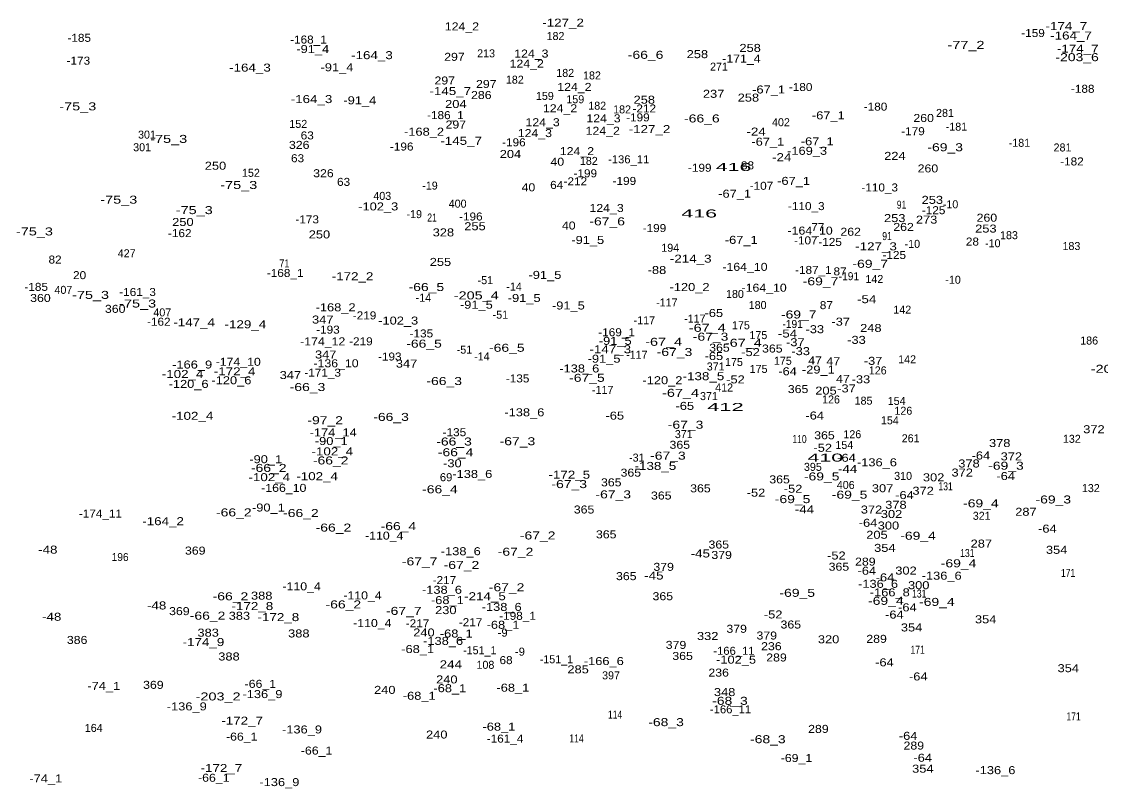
# Model space of a CAD drawing. Extents: x -658110 to -655750, y -1000429 to -997657.
# Drawn here: x -657542 to -657003, y -999113 to -998730 of the extents above; entities that cross this region are included whole.
import ezdxf
from ezdxf.enums import TextEntityAlignment as Align

# ---------------------------------------------------------------- set-up
doc = ezdxf.new("R2010")
doc.units = 0
doc.header["$LTSCALE"] = 1.6
doc.layers.add('24', color=7, linetype='Continuous')

msp = doc.modelspace()

# ---------------------------------------------------------------- texts
at = {"layer": '24'}
for s, width, p in [('124_2', 1.15, (-657322.15, -998734.24)), ('-127_2', 1.25, (-657271.59, -998732.37)), ('-174_7', 1.25, (-657020.03, -998734.08)), ('-185', 1.1, (-657513.451, -998739.96)), ('-159', 1.1, (-657036.68, -998737.56)), ('-164_7', 1.25, (-657017.691, -998738.81)), ('-168_1', 1.1, (-657398.88, -998740.82)), ('258', 1.2, (-657178.09, -998745)), ('-77_2', 1.35, (-657070.191, -998743.49)), ('-174_7', 1.25, (-657014.331, -998745.38)), ('-91_4', 1.2, (-657396.72, -998745.56)), ('-164_3', 1.25, (-657367.13, -998748.62)), ('297', 1.15, (-657325.89, -998749.45)), ('124_3', 1.15, (-657287.449, -998747.82)), ('-66_6', 1.3, (-657230.34, -998748.45)), ('258', 1.2, (-657204.459, -998748.11)), ('-171_4', 1.15, (-657182.45, -998750.33)), ('-203_6', 1.3, (-657014.64, -998749.63)), ('-173', 1.1, (-657513.88, -998751.37)), ('-164_3', 1.25, (-657428.11, -998754.84)), ('-91_4', 1.2, (-657384.62, -998754.67)), ('124_2', 1.15, (-657289.77, -998752.86)), ('297', 1.15, (-657330.74, -998761.28)), ('-145_7', 1.25, (-657327.97, -998766.56)), ('297', 1.15, (-657309.99, -998763.03)), ('124_2', 1.15, (-657265.929, -998764.49)), ('-67_1', 1.2, (-657168.86, -998765.78)), ('-180', 1.1, (-657152.851, -998764.55)), ('-188', 1.1, (-657011.841, -998765.43)), ('-164_3', 1.25, (-657397.33, -998770.57)), ('-91_4', 1.2, (-657373.19, -998771.19)), ('286', 1.15, (-657312.48, -998768.55)), ('258', 1.2, (-657231.01, -998770.89)), ('237', 1.2, (-657196.34, -998767.94)), ('258', 1.2, (-657178.959, -998769.83)), ('-75_3', 1.35, (-657514.17, -998774.22)), ('204', 1.2, (-657325.199, -998773.03)), ('124_2', 1.15, (-657273.1, -998775.16)), ('-212', 1.1, (-657231.01, -998775.27)), ('-180', 1.1, (-657115.41, -998774.34)), ('-186_1', 1.1, (-657330.421, -998778.59)), ('124_3', 1.15, (-657281.819, -998782.14)), ('124_3', 1.15, (-657251.39, -998780.2)), ('-199', 1.1, (-657234.189, -998779.72)), ('-66_6', 1.3, (-657202.22, -998780.25)), ('-67_1', 1.2, (-657139.01, -998778.69)), ('260', 1.15, (-657091.361, -998780.02)), ('-168_2', 1.2, (-657341.101, -998786.88)), ('297', 1.15, (-657325.21, -998783.29)), ('124_3', 1.15, (-657285.699, -998787.57)), ('124_2', 1.15, (-657251.77, -998786.41)), ('-127_2', 1.25, (-657228.39, -998785.57)), ('-24', 1.25, (-657175.08, -998786.81)), ('-179', 1.1, (-657096.689, -998786.63)), ('-75_3', 1.35, (-657468.72, -998790.48)), ('326', 1.15, (-657403.48, -998793.47)), ('63', 1.1, (-657399.48, -998788.73)), ('-145_7', 1.25, (-657322.55, -998791.44)), ('-196', 1.1, (-657296.189, -998792.18)), ('-67_1', 1.2, (-657169.25, -998791.87)), ('-67_1', 1.2, (-657144.54, -998791.68)), ('-196', 1.1, (-657352.26, -998794.29)), ('204', 1.2, (-657297.9, -998798.03)), ('124_2', 1.15, (-657264.66, -998796.6)), ('-169_3', 1.2, (-657149.62, -998796.43)), ('224', 1.2, (-657105.73, -998798.96)), ('-69_3', 1.3, (-657080.59, -998794.64)), ('250', 1.2, (-657445.34, -998803.88)), ('63', 1.1, (-657404.31, -998800.14)), ('40', 1.15, (-657274.48, -998801.88)), ('-136_11', 1.05, (-657238.811, -998800.68)), ('416', 2, (-657186.368, -998804.5)), ('88', 1.1, (-657179.41, -998803.69)), ('-24', 1.25, (-657162.29, -998799.61)), ('-182', 1.1, (-657017.24, -998801.74)), ('326', 1.15, (-657391.37, -998807.63)), ('-199', 1.1, (-657260.49, -998807.67)), ('-199', 1.1, (-657203.28, -998804.89)), ('260', 1.15, (-657089.231, -998805.23)), ('-75_3', 1.35, (-657433.71, -998813.5)), ('63', 1.1, (-657381.3, -998811.95)), ('40', 1.15, (-657288.919, -998814.68)), ('64', 1.1, (-657274.77, -998813.47)), ('-212', 1.1, (-657265.481, -998811.67)), ('-199', 1.1, (-657240.959, -998811.47)), ('-107', 1.1, (-657172.43, -998813.91)), ('-67_1', 1.2, (-657156.36, -998811.46)), ('-110_3', 1.1, (-657113.33, -998814.74)), ('-75_3', 1.35, (-657493.67, -998820.85)), ('-67_1', 1.2, (-657185.83, -998817.86)), ('253', 1.2, (-657087.01, -998820.94)), ('-75_3', 1.35, (-657455.95, -998826.07)), ('-102_3', 1.2, (-657363.98, -998824.22)), ('124_3', 1.15, (-657249.84, -998825)), ('-110_3', 1.1, (-657150.02, -998824.05)), ('91', 0.8, (-657102.4, -998823.33)), ('-125', 1.1, (-657086.37, -998826.11)), ('-173', 1.1, (-657399.5, -998830.69)), ('21', 0.8, (-657337.09, -998829.77)), ('-196', 1.1, (-657317.699, -998829.25)), ('-67_6', 1.3, (-657249.559, -998831.69)), ('416', 2, (-657203.548, -998827.74)), ('253', 1.2, (-657105.809, -998830.05)), ('273', 1.2, (-657089.88, -998830.82)), ('260', 1.15, (-657059.76, -998829.86)), ('-75_3', 1.35, (-657535.83, -998836.72)), ('250', 1.2, (-657461.63, -998832)), ('328', 1.2, (-657331.419, -998837.2)), ('255', 1.2, (-657315.62, -998834.12)), ('40', 1.15, (-657268.76, -998833.78)), ('-199', 1.1, (-657225.929, -998835.04)), ('-164_10', 1.15, (-657148.111, -998836.31)), ('77', 1.1, (-657144.27, -998834.56)), ('262', 1.15, (-657127.84, -998836.87)), ('262', 1.15, (-657101.4, -998834.47)), ('253', 1.2, (-657060.25, -998835.29)), ('-162', 1.1, (-657463.2, -998837.57)), ('250', 1.2, (-657393.38, -998838.21)), ('-91_5', 1.2, (-657259.26, -998840.98)), ('-67_1', 1.2, (-657182.53, -998840.93)), ('-107', 1.1, (-657150.26, -998841.19)), ('-125', 1.1, (-657138.12, -998841.96)), ('91', 0.8, (-657109.671, -998839.04)), ('28', 1.1, (-657066.98, -998841.78)), ('-127_3', 1.25, (-657115.17, -998844.18)), ('82', 1.1, (-657525.52, -998850.78)), ('71', 0.85, (-657410.941, -998852.72)), ('255', 1.2, (-657332.88, -998851.96)), ('-214_3', 1.25, (-657207.79, -998850.32)), ('-69_7', 1.3, (-657118.069, -998852.89)), ('-125', 1.1, (-657106.051, -998848.49)), ('20', 1.1, (-657513.26, -998858.56)), ('-168_1', 1.1, (-657410.51, -998857.48)), ('-91_5', 1.2, (-657280.671, -998858.45)), ('-88', 1.2, (-657224.67, -998856.01)), ('-164_10', 1.15, (-657180.671, -998854.42)), ('-187_1', 1.1, (-657146.481, -998855.96)), ('87', 1.1, (-657133.13, -998856.68)), ('-172_2', 1.25, (-657376.82, -998859.11)), ('-69_7', 1.3, (-657142.9, -998861.63)), ('-191', 0.95, (-657128.73, -998859.08)), ('-185', 1.1, (-657534.961, -998864.42)), ('-75_3', 1.35, (-657507.78, -998868.44)), ('-161_3', 1.1, (-657484.291, -998867)), ('-66_5', 1.3, (-657339.93, -998864.51)), ('-205_4', 1.35, (-657315, -998868.68)), ('-120_2', 1.2, (-657208.38, -998864.51)), ('-164_10', 1.15, (-657171.091, -998864.85)), ('360', 1.15, (-657532.841, -998869.97)), ('-75_3', 1.35, (-657484.24, -998872.75)), ('-168_2', 1.2, (-657385.291, -998874.64)), ('-91_5', 1.2, (-657314.941, -998873.34)), ('-91_5', 1.2, (-657291.041, -998869.98)), ('-91_5', 1.2, (-657268.951, -998873.73)), ('87', 1.1, (-657139.99, -998873.56)), ('-54', 1.25, (-657119.85, -998870.58)), ('360', 1.15, (-657495.461, -998875.41)), ('-219', 1.1, (-657370.83, -998878.68)), ('-65', 1.2, (-657196.24, -998877.48)), ('-69_7', 1.3, (-657153.799, -998878.22)), ('-162', 1.1, (-657473.68, -998881.84)), ('-147_4', 1.25, (-657456.01, -998882.15)), ('-129_4', 1.25, (-657430.39, -998883.12)), ('347', 1.2, (-657391.71, -998880.76)), ('-102_3', 1.2, (-657354, -998881.27)), ('-67_4', 1.35, (-657199.5, -998884.89)), ('-191', 0.95, (-657156.86, -998882.99)), ('-33', 1.2, (-657145.77, -998885.58)), ('-37', 1.2, (-657132.821, -998881.81)), ('248', 1.2, (-657117.74, -998884.96)), ('-193', 1.1, (-657389.13, -998885.8)), ('-135', 1.1, (-657342.421, -998887.7)), ('-169_1', 1.1, (-657244.84, -998887.11)), ('-67_3', 1.3, (-657197.851, -998889.31)), ('-54', 1.25, (-657159.41, -998887.74)), ('-33', 1.2, (-657124.93, -998890.92)), ('-174_12', 1.15, (-657391.73, -998891.67)), ('-219', 1.1, (-657372.66, -998891.65)), ('-66_5', 1.3, (-657341.1, -998892.81)), ('-66_5', 1.3, (-657299.71, -998894.87)), ('-147_3', 1.25, (-657248.01, -998895.62)), ('-91_5', 1.2, (-657245.53, -998891.4)), ('-67_4', 1.35, (-657221.311, -998891.88)), ('365', 1.15, (-657193.43, -998894.81)), ('-67_4', 1.35, (-657181.481, -998892.37)), ('365', 1.15, (-657167.01, -998895.25)), ('-37', 1.2, (-657155.5, -998892.09)), ('-174_10', 1.15, (-657433.98, -998901.87)), ('347', 1.2, (-657390.23, -998898.23)), ('-193', 1.1, (-657358.22, -998899.24)), ('-91_5', 1.2, (-657251.101, -998900.33)), ('-67_3', 1.3, (-657215.89, -998896.97)), ('-65', 1.2, (-657196.21, -998898.99)), ('-52', 1.2, (-657177.89, -998897.03)), ('-33', 1.2, (-657152.84, -998896.55)), ('47', 1.15, (-657145.64, -998901.2)), ('47', 1.15, (-657136.53, -998901.59)), ('-37', 1.2, (-657116.63, -998901.4)), ('-166_9', 1.2, (-657457, -998903.25)), ('-172_4', 1.25, (-657435.76, -998906.63)), ('-171_3', 1.1, (-657391.77, -998907.3)), ('-136_10', 1.15, (-657385.071, -998902.62)), ('347', 1.2, (-657349.83, -998902.77)), ('-138_6', 1.2, (-657263.49, -998905.21)), ('-64', 1.2, (-657159.38, -998906.61)), ('-29_1', 1.2, (-657144, -998905.76)), ('-203_4', 1.35, (-656996.6, -998905.38)), ('-102_4', 1.25, (-657461.78, -998907.97)), ('-120_6', 1.2, (-657437.38, -998911.1)), ('347', 1.2, (-657407.9, -998908.49)), ('-66_3', 1.3, (-657331.02, -998911.49)), ('-135', 1.1, (-657294.321, -998910.18)), ('-67_5', 1.3, (-657259.671, -998909.88)), ('-120_2', 1.2, (-657221.929, -998911.09)), ('-138_5', 1.25, (-657201.429, -998909.07)), ('-52', 1.2, (-657185.42, -998910.68)), ('47', 1.15, (-657131.68, -998910.41)), ('-33', 1.2, (-657122.71, -998910.61)), ('-120_6', 1.2, (-657458.78, -998912.93)), ('-66_3', 1.3, (-657399.35, -998914.49)), ('-67_4', 1.35, (-657212.88, -998917.39)), ('365', 1.15, (-657154.12, -998915.51)), ('205', 1.2, (-657140.179, -998916.29)), ('-37', 1.2, (-657129.91, -998915.18)), ('-102_4', 1.25, (-657456.84, -998928.88)), ('-138_6', 1.2, (-657290.951, -998927.11)), ('-65', 1.2, (-657245.74, -998928.77)), ('-65', 1.2, (-657210.75, -998923.91)), ('412', 2.05, (-657190.443, -998924.45)), ('-64', 1.2, (-657145.811, -998928.72)), ('-97_2', 1.3, (-657390.51, -998931.07)), ('-66_3', 1.3, (-657357.58, -998929.42)), ('-67_3', 1.3, (-657210.361, -998933.33)), ('-174_14', 1.2, (-657386.5, -998937.16)), ('-135', 1.1, (-657325.91, -998937.06)), ('365', 1.15, (-657140.94, -998938.59)), ('372', 1.2, (-657006.24, -998935.58)), ('-90_1', 1.2, (-657387.471, -998941.48)), ('-66_3', 1.3, (-657326.1, -998941.72)), ('-67_3', 1.3, (-657294.41, -998941.58)), ('365', 1.15, (-657213.25, -998943.35)), ('110', 0.8, (-657153.42, -998940.5)), ('-52', 1.2, (-657141.8, -998944.84)), ('378', 1.2, (-657053.34, -998942.48)), ('-102_4', 1.25, (-657386.939, -998946.65)), ('-66_4', 1.3, (-657325.311, -998947.07)), ('-67_3', 1.3, (-657219.191, -998948.77)), ('410', 2, (-657140.509, -998949.75)), ('-64', 1.2, (-657129.91, -998949.85)), ('-64', 1.2, (-657062.75, -998948.7)), ('372', 1.2, (-657047.53, -998949.15)), ('-90_1', 1.2, (-657420.221, -998950.56)), ('-66_2', 1.3, (-657418.72, -998954.91)), ('-66_2', 1.3, (-657387.75, -998951.17)), ('-30', 1.2, (-657326.92, -998952.59)), ('-138_5', 1.25, (-657225.439, -998953.92)), ('-44', 1.25, (-657129.36, -998955.44)), ('-136_6', 1.2, (-657114.71, -998952.11)), ('378', 1.2, (-657068.7, -998952.69)), ('-69_3', 1.3, (-657050.21, -998953.81)), ('-102_4', 1.25, (-657418.439, -998959.53)), ('-102_4', 1.25, (-657394.53, -998959.04)), ('69', 1.05, (-657330.07, -998959.55)), ('-138_6', 1.2, (-657316.971, -998957.93)), ('-172_5', 1.25, (-657268.48, -998958.3)), ('365', 1.15, (-657237.73, -998957.27)), ('365', 1.15, (-657163.38, -998960.65)), ('-69_5', 1.3, (-657142.33, -998959.16)), ('302', 1.2, (-657086.37, -998959.62)), ('372', 1.2, (-657072.07, -998957.22)), ('-64', 1.2, (-657050.351, -998958.98)), ('-166_10', 1.15, (-657411.199, -998964.89)), ('-66_4', 1.3, (-657333.16, -998965.59)), ('-67_3', 1.3, (-657268.52, -998963)), ('365', 1.15, (-657247.52, -998962.12)), ('365', 1.15, (-657202.93, -998965.11)), ('-52', 1.2, (-657156.63, -998965.32)), ('307', 1.2, (-657111.89, -998965.07)), ('372', 1.2, (-657091.63, -998966.32)), ('131', 0.8, (-657080.39, -998964.09)), ('-67_3', 1.3, (-657246.52, -998968.14)), ('365', 1.15, (-657222.51, -998968.72)), ('-52', 1.2, (-657175.16, -998967.27)), ('-69_5', 1.3, (-657156.87, -998970.51)), ('-69_5', 1.3, (-657128.38, -998968.28)), ('-64', 1.2, (-657100.941, -998968.48)), ('-69_3', 1.3, (-657026.56, -998970.68)), ('-66_2', 1.3, (-657436.18, -998977.15)), ('-90_1', 1.2, (-657418.89, -998974.71)), ('365', 1.15, (-657261.09, -998975.7)), ('-44', 1.25, (-657150.91, -998975.63)), ('372', 1.2, (-657117.42, -998975.72)), ('378', 1.2, (-657105.22, -998973.33)), ('-69_4', 1.3, (-657062.75, -998972.61)), ('287', 1.2, (-657040.23, -998976.82)), ('-174_11', 1.1, (-657502.87, -998977.75)), ('-164_2', 1.25, (-657471.53, -998981.53)), ('-66_2', 1.3, (-657402.65, -998977.46)), ('-64', 1.2, (-657119.15, -998982.34)), ('302', 1.2, (-657107.41, -998977.95)), ('-66_2', 1.3, (-657386.39, -998984.73)), ('-66_4', 1.3, (-657353.9, -998984.01)), ('365', 1.15, (-657250.04, -998988.11)), ('300', 1.2, (-657108.959, -998983.7)), ('-64', 1.2, (-657029.51, -998985.26)), ('-110_4', 1.15, (-657360.99, -998988.74)), ('-67_2', 1.3, (-657284.301, -998988.67)), ('365', 1.15, (-657193.77, -998993.2)), ('205', 1.2, (-657114.689, -998988.32)), ('-69_4', 1.3, (-657094.16, -998988.81)), ('287', 1.2, (-657062.52, -998992.73)), ('-48', 1.25, (-657529.16, -998995.74)), ('369', 1.15, (-657455.46, -998996.23)), ('-138_6', 1.2, (-657322.731, -998996.54)), ('-67_2', 1.3, (-657295.351, -998996.81)), ('-45', 1.25, (-657202.99, -998997.67)), ('379', 1.15, (-657192.33, -998998.41)), ('-52', 1.2, (-657134.98, -998998.69)), ('354', 1.2, (-657110.76, -998994.88)), ('131', 0.8, (-657069.53, -998997.45)), ('354', 1.2, (-657024.88, -998995.85)), ('196', 0.95, (-657493, -998999.45)), ('-67_7', 1.3, (-657343.28, -999001.64)), ('-67_2', 1.3, (-657322.39, -999003.41)), ('379', 1.15, (-657221.32, -999004.35)), ('365', 1.15, (-657133.72, -999004.29)), ('289', 1.15, (-657120.51, -999001.75)), ('-69_4', 1.3, (-657073.9, -999002.58)), ('365', 1.15, (-657240.01, -999009)), ('-45', 1.25, (-657226.2, -999008.7)), ('-64', 1.2, (-657119.76, -999006.29)), ('-64', 1.2, (-657110.691, -999009.63)), ('302', 1.2, (-657100.179, -999006.22)), ('-136_6', 1.2, (-657082.35, -999008.77)), ('171', 0.8, (-657019.14, -999007.37)), ('-110_4', 1.15, (-657402.28, -999014.09)), ('-217', 1.1, (-657330.9, -999010.98)), ('-67_2', 1.3, (-657299.821, -999014.56)), ('-136_6', 1.2, (-657114.15, -999012.84)), ('300', 1.2, (-657093.829, -999013.52)), ('-66_2', 1.3, (-657437.86, -999019.07)), ('388', 1.2, (-657422.23, -999018.73)), ('-110_4', 1.15, (-657371.84, -999018.61)), ('-138_6', 1.2, (-657332.14, -999015.82)), ('-214_5', 1.25, (-657310.63, -999019.04)), ('365', 1.15, (-657221.74, -999019.03)), ('-69_5', 1.3, (-657154.55, -999017.35)), ('-166_8', 1.2, (-657108.29, -999017.11)), ('131', 0.8, (-657093.57, -999017.71)), ('-48', 1.25, (-657474.74, -999023.65)), ('-172_8', 1.25, (-657426.89, -999023.95)), ('-66_2', 1.3, (-657381.44, -999023.13)), ('-68_1', 1.2, (-657329.431, -999020.98)), ('-138_6', 1.2, (-657302.28, -999024.38)), ('-69_4', 1.3, (-657110.25, -999021.34)), ('-64', 1.2, (-657099.481, -999024.6)), ('-69_4', 1.3, (-657084.75, -999021.88)), ('-48', 1.25, (-657527.21, -999029.3)), ('369', 1.15, (-657463.4, -999026.48)), ('-66_2', 1.3, (-657449.3, -999028.76)), ('383', 1.2, (-657433.39, -999028.8)), ('-172_8', 1.25, (-657413.9, -999029.48)), ('-67_7', 1.3, (-657351.22, -999026.37)), ('230', 1.2, (-657330.199, -999025.97)), ('-198_1', 1.1, (-657294.361, -999028.83)), ('-52', 1.2, (-657166.58, -999028.15)), ('-64', 1.2, (-657105.99, -999028.21)), ('354', 1.2, (-657060.36, -999030.57)), ('-110_4', 1.15, (-657366.949, -999032.44)), ('-217', 1.1, (-657344.34, -999032.58)), ('-217', 1.1, (-657317.84, -999032.01)), ('-68_1', 1.2, (-657301.611, -999033.31)), ('379', 1.15, (-657184.82, -999035.31)), ('365', 1.15, (-657157.76, -999033.18)), ('354', 1.2, (-657097.39, -999034.64)), ('386', 1.15, (-657514.49, -999040.88)), ('-174_9', 1.25, (-657451.37, -999041.95)), ('383', 1.2, (-657449.01, -999037.24)), ('388', 1.2, (-657403.689, -999037.64)), ('240', 1.2, (-657341.14, -999037.15)), ('-138_6', 1.2, (-657331.561, -999041.37)), ('-68_1', 1.2, (-657324.99, -999037.68)), ('-9', 1.05, (-657301.8, -999037.24)), ('332', 1.2, (-657199.309, -999038.93)), ('379', 1.15, (-657169.79, -999038.67)), ('320', 1.2, (-657138.88, -999040.56)), ('289', 1.15, (-657114.89, -999040.34)), ('-68_1', 1.2, (-657344.28, -999045.44)), ('-9', 1.05, (-657293.17, -999046.74)), ('379', 1.15, (-657215.14, -999043.37)), ('-166_11', 1.05, (-657186.189, -999046.32)), ('236', 1.15, (-657167.47, -999044.02)), ('171', 0.8, (-657094.361, -999045.77)), ('388', 1.2, (-657438.59, -999049.16)), ('68', 1.1, (-657300.09, -999050.98)), ('-166_6', 1.2, (-657251.23, -999051.44)), ('365', 1.15, (-657211.85, -999048.89)), ('-102_5', 1.2, (-657185.13, -999050.75)), ('289', 1.15, (-657164.91, -999049.65)), ('-64', 1.2, (-657110.941, -999052.07)), ('244', 1.25, (-657327.71, -999053.1)), ('285', 1.2, (-657264.079, -999055.58)), ('236', 1.15, (-657193.83, -999057.21)), ('354', 1.2, (-657019.059, -999055)), ('369', 1.15, (-657476.39, -999063.33)), ('-66_1', 1.15, (-657422.92, -999062.83)), ('240', 1.2, (-657329.699, -999060.62)), ('-64', 1.2, (-657094.051, -999059.13)), ('-74_1', 1.2, (-657501.18, -999063.89)), ('-136_9', 1.2, (-657421.86, -999067.95)), ('240', 1.2, (-657360.72, -999065.85)), ('-68_1', 1.2, (-657343.5, -999068.79)), ('-68_1', 1.2, (-657328.191, -999065.01)), ('-68_1', 1.2, (-657296.691, -999064.74)), ('348', 1.2, (-657190.84, -999066.95)), ('-136_9', 1.2, (-657459.69, -999074.1)), ('-203_2', 1.35, (-657444.04, -999069.13)), ('-68_3', 1.3, (-657188.18, -999071.31)), ('114', 0.8, (-657245.6, -999078.19)), ('-166_11', 1.05, (-657187.89, -999075.55)), ('171', 0.8, (-657016.431, -999079.12)), ('-172_7', 1.25, (-657432.01, -999081.23)), ('-68_1', 1.2, (-657303.671, -999084.21)), ('-68_3', 1.3, (-657220.12, -999081.97)), ('-66_1', 1.15, (-657432.23, -999089.2)), ('-136_9', 1.2, (-657402.09, -999085.62)), ('240', 1.2, (-657334.74, -999088.16)), ('-161_4', 1.1, (-657300.61, -999090.2)), ('114', 0.8, (-657264.89, -999090.12)), ('-68_3', 1.3, (-657169.23, -999090.5)), ('289', 1.15, (-657143.97, -999085.34)), ('-64', 1.2, (-657099.111, -999088.82)), ('289', 1.15, (-657096.28, -999093.68)), ('-66_1', 1.15, (-657394.81, -999096.18)), ('-69_1', 1.15, (-657154.93, -999099.9)), ('-64', 1.2, (-657091.821, -999099.77)), ('-172_7', 1.25, (-657442.38, -999104.89)), ('354', 1.2, (-657091.76, -999105.23)), ('-136_6', 1.2, (-657055.48, -999105.96)), ('-74_1', 1.2, (-657530.18, -999110.12)), ('-66_1', 1.15, (-657446.19, -999109.76)), ('-136_9', 1.2, (-657413.41, -999111.94))]:
    msp.add_text(s, height=4, dxfattribs=dict(at, width=width)).set_placement(p, align=Align.CENTER)
for s, p in [('182', (-657275.37, -998739.07)), ('213', (-657310.079, -998747.72)), ('271', (-657193.65, -998754.36)), ('182', (-657295.72, -998760.88)), ('182', (-657270.52, -998757.49)), ('182', (-657257.14, -998758.75)), ('159', (-657280.711, -998769.01)), ('159', (-657265.49, -998770.66)), ('182', (-657254.53, -998773.88)), ('182', (-657242.1, -998775.73)), ('281', (-657080.689, -998777.49)), ('152', (-657403.959, -998782.98)), ('402', (-657162.685, -998782.14)), ('301', (-657479.59, -998788.33)), ('-181', (-657074.971, -998784.36)), ('-181', (-657043.481, -998792.43)), ('301', (-657482.02, -998794.64)), ('281', (-657021.949, -998794.75)), ('182', (-657258.74, -998801.47)), ('152', (-657427.62, -998807.42)), ('-19', (-657338.12, -998813.82)), ('403', (-657361.975, -998818.96)), ('400', (-657324.289, -998822.84)), ('-10', (-657077.921, -998823.16)), ('-19', (-657345.97, -998828.07)), ('183', (-657048.709, -998838.59)), ('427', (-657489.727, -998847.63)), ('194', (-657218.03, -998844.87)), ('-10', (-657097.01, -998842.92)), ('-10', (-657056.791, -998842.63)), ('183', (-657017.5, -998844.02)), ('-51', (-657310.451, -998861.07)), ('142', (-657116, -998860.49)), ('-10', (-657076.66, -998860.86)), ('407', (-657521.361, -998865.92)), ('-14', (-657296.09, -998864.28)), ('180', (-657185.68, -998867.97)), ('-14', (-657341.42, -998869.84)), ('-117', (-657219.74, -998872.22)), ('180', (-657174.34, -998873.5)), ('407', (-657471.921, -998877.17)), ('-51', (-657302.941, -998878.34)), ('-117', (-657205.73, -998880.28)), ('142', (-657102.049, -998875.81)), ('-117', (-657230.97, -998881.14)), ('175', (-657182.691, -998883.63)), ('175', (-657173.971, -998888.53)), ('-51', (-657320.89, -998895.8)), ('186', (-657008.63, -998891.25)), ('-14', (-657312.19, -998899.17)), ('-117', (-657234.72, -998898.33)), ('175', (-657161.75, -998901.37)), ('142', (-657099.62, -998900.64)), ('371', (-657195.321, -998904.21)), ('175', (-657186.181, -998901.96)), ('175', (-657173.87, -998905.45)), ('126', (-657114.311, -998906.17)), ('-117', (-657251.8, -998915.91)), ('412', (-657191.09, -998914.72)), ('371', (-657198.681, -998919.01)), ('126', (-657137.671, -998920.7)), ('185', (-657121.41, -998921.3)), ('154', (-657104.85, -998921.43)), ('126', (-657101.51, -998926.34)), ('154', (-657108.25, -998931.13)), ('371', (-657211.27, -998938.01)), ('126', (-657127.01, -998938.07)), ('154', (-657131.02, -998943.44)), ('261', (-657097.851, -998940.1)), ('132', (-657017.299, -998940.37)), ('-31', (-657234.74, -998949.76)), ('395', (-657146.733, -998954.38)), ('310', (-657101.63, -998958.9)), ('406', (-657130.311, -998963.43)), ('132', (-657007.799, -998965)), ('321', (-657062.35, -998978.85)), ('-151_1', (-657313.23, -999046.03)), ('-151_1', (-657274.92, -999050.54)), ('108', (-657310.41, -999053.32)), ('397', (-657247.628, -999058.58)), ('164', (-657506.2, -999084.86))]:
    msp.add_text(s, height=4, dxfattribs=at).set_placement(p, align=Align.CENTER)

doc.saveas('drawing.dxf')
